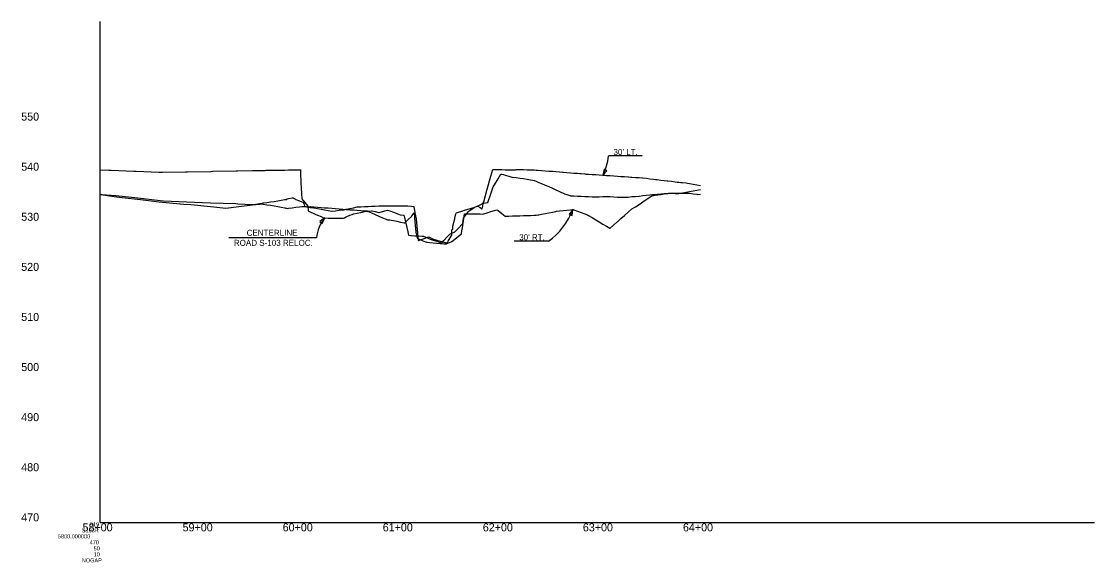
# Model space of a CAD drawing. Extents: x 1961504 to 1964196, y 1107046 to 1115093.
# Drawn here: x 1961505 to 1962577, y 1114552 to 1115093 of the extents above; entities that cross this region are included whole.
import ezdxf

# ---------------------------------------------------------------- set-up
doc = ezdxf.new("R2010")
doc.units = 0
for name, color, linetype in [('Level 40', 7, 'Continuous'), ('Level 41', 7, 'Continuous'), ('Level 42', 7, 'Continuous'), ('Level 63', 7, 'Continuous')]:
    doc.layers.add(name, color=color, linetype=linetype)

msp = doc.modelspace()

# ---------------------------------------------------------------- linework, layer by layer
at = {"layer": 'Level 40'}
for points in [[(1961583.7, 1114944.4), (1961592.3, 1114944), (1961594.7, 1114944), (1961617.3, 1114943.1), (1961619.7, 1114943), (1961642.3, 1114942.2), (1961642.8, 1114942.1), (1961645.9, 1114942), (1961668.8, 1114942.4), (1961670.9, 1114942.5), (1961694.1, 1114942.9), (1961695.9, 1114943), (1961719.5, 1114943.4), (1961720.9, 1114943.4), (1961735.7, 1114943.7), (1961739.3, 1114943.8), (1961742.9, 1114943.8), (1961744.8, 1114943.9), (1961745.9, 1114943.9), (1961745.9, 1114943.9), (1961746.5, 1114943.9), (1961748.4, 1114943.9), (1961749.5, 1114944), (1961750.2, 1114944), (1961753.8, 1114944), (1961757.4, 1114944.1), (1961761, 1114944.2), (1961764.6, 1114944.3), (1961768.2, 1114944.3), (1961771.8, 1114944.4), (1961773.4, 1114944.4), (1961774.2, 1114944.5), (1961775.4, 1114944.5), (1961779.1, 1114944.6), (1961782.7, 1114944.6), (1961783.7, 1114944.6), (1961783.8, 1114944.7), (1961783.9, 1114941.5), (1961784.2, 1114931.5), (1961785.3, 1114915.4), (1961786.3, 1114914.3), (1961789.9, 1114909.8), (1961791.2, 1114908.1), (1961791.5, 1114903.4), (1961793.5, 1114902.4), (1961797.1, 1114900.8), (1961798.5, 1114900.1), (1961800.7, 1114899.2), (1961804.3, 1114897.8), (1961806.9, 1114896.7), (1961807.9, 1114896.4), (1961808, 1114896.4), (1961811.6, 1114896.3), (1961815.2, 1114896.3), (1961818.8, 1114896.3), (1961822.4, 1114896.3), (1961826, 1114896.2), (1961826.8, 1114896.2), (1961827.9, 1114896.6), (1961829.6, 1114897.4), (1961833.2, 1114899.1), (1961835.4, 1114900), (1961836.8, 1114900.4), (1961840.4, 1114901.2), (1961844.1, 1114902), (1961847.7, 1114902.9), (1961848.7, 1114903.1), (1961851.3, 1114903.3), (1961854.9, 1114903.6), (1961855.4, 1114903.6), (1961858.5, 1114902.8), (1961862.1, 1114901.9), (1961862.3, 1114901.9), (1961865.7, 1114902.8), (1961869.3, 1114903.9), (1961870.6, 1114904.2), (1961873, 1114903.4), (1961876.6, 1114902.1), (1961880.2, 1114900.9), (1961883.4, 1114899.7), (1961883.8, 1114899.7), (1961886.7, 1114899.2), (1961887.3, 1114898.5), (1961887.4, 1114898.3), (1961887.8, 1114896.9), (1961891, 1114882.7), (1961891.8, 1114879.2), (1961893.7, 1114878.9), (1961894.6, 1114878.9), (1961898.2, 1114878.7), (1961901.8, 1114878.6), (1961905.5, 1114878.4), (1961906.8, 1114878.3), (1961909.1, 1114877.2), (1961912.7, 1114875.5), (1961913.4, 1114875.1), (1961916.3, 1114874.2), (1961919.9, 1114873.2), (1961923.5, 1114872.1), (1961925.1, 1114871.6), (1961927.1, 1114873.8)], [(1961939.6, 1114901.5), (1961941.6, 1114902.1), (1961945.2, 1114903.2), (1961948.8, 1114904.4), (1961952.4, 1114905.5), (1961956, 1114906.7), (1961958, 1114907.3), (1961959.6, 1114907.8), (1961960.9, 1114908.2), (1961963.2, 1114906.8), (1961965.1, 1114905.7), (1961965.2, 1114905.7), (1961965.7, 1114907), (1961966.8, 1114912.4), (1961966.9, 1114912.5), (1961970.5, 1114925.3), (1961974.1, 1114938.1), (1961976, 1114944.8), (1961977.7, 1114944.8), (1961977.9, 1114944.8), (1961981.3, 1114944.8), (1961984.9, 1114944.7), (1961988.5, 1114944.6), (1961992.1, 1114944.6), (1961995.7, 1114944.5), (1961997.1, 1114944.5), (1961998.7, 1114944.6), (1961999.4, 1114944.7), (1961999.4, 1114944.7), (1962001.5, 1114944.8), (1962003, 1114944.8), (1962006.6, 1114944.7), (1962010.2, 1114944.6), (1962013.8, 1114944.5), (1962017.4, 1114944.4), (1962019.2, 1114944.3), (1962020.5, 1114944.2), (1962020.8, 1114944.2), (1962021, 1114944.2), (1962024.6, 1114943.9), (1962028.2, 1114943.6), (1962031.9, 1114943.3), (1962035.5, 1114943.1), (1962039.1, 1114942.8), (1962042.6, 1114942.5), (1962042.7, 1114942.5), (1962045.5, 1114942.2), (1962046.3, 1114942.2), (1962049.9, 1114941.9), (1962053.5, 1114941.6), (1962057.1, 1114941.3), (1962060.7, 1114941), (1962062.8, 1114940.8), (1962064.4, 1114940.7), (1962068, 1114940.4), (1962068.5, 1114940.3), (1962071.6, 1114940.1), (1962075.2, 1114939.9), (1962078.8, 1114939.7), (1962082.4, 1114939.4), (1962086, 1114939.2), (1962087.9, 1114939), (1962089.6, 1114938.9), (1962092.9, 1114938.7), (1962093.3, 1114938.7), (1962096.9, 1114938.4), (1962100.5, 1114938.2), (1962104.1, 1114937.9), (1962107.7, 1114937.7), (1962111.3, 1114937.4), (1962111.5, 1114937.4), (1962113.9, 1114937.3), (1962114.9, 1114937.2), (1962118.5, 1114936.9), (1962122.1, 1114936.7), (1962125.6, 1114936.4), (1962125.8, 1114936.4), (1962129.4, 1114936), (1962133, 1114935.5), (1962136.6, 1114935.1), (1962138.5, 1114934.9), (1962140.2, 1114934.7), (1962143.8, 1114934.3), (1962147.4, 1114933.9), (1962150.4, 1114933.6), (1962151, 1114933.5), (1962154.6, 1114933), (1962158.3, 1114932.5), (1962160.1, 1114932.3), (1962161.9, 1114932.1), (1962164, 1114931.8), (1962165.5, 1114931.7), (1962169.1, 1114931.4), (1962170.4, 1114931.2), (1962172.7, 1114930.8), (1962176.3, 1114930.1), (1962179.9, 1114929.4), (1962183.5, 1114928.7), (1962183.7, 1114928.7)], [(1961927.1, 1114873.8), (1961930.7, 1114877.9), (1961932.9, 1114880.3), (1961934.3, 1114880.9), (1961937.5, 1114882.3), (1961938, 1114882.7), (1961941.6, 1114886.3), (1961945.2, 1114889.9), (1961946.1, 1114890.8), (1961946.8, 1114896.1), (1961948.8, 1114898.9), (1961951.3, 1114902.6), (1961952.4, 1114903.4), (1961956, 1114905.9), (1961957.8, 1114907.2), (1961959.6, 1114908), (1961963.2, 1114909.7), (1961966.4, 1114911.2), (1961966.9, 1114911.2), (1961967, 1114911.2), (1961970.5, 1114911.7), (1961971.1, 1114911.8), (1961974.1, 1114920.5), (1961976.5, 1114927.5), (1961977.7, 1114929.5), (1961981.3, 1114935.6), (1961984, 1114940.1), (1961984.3, 1114940.1), (1961984.9, 1114940), (1961986.7, 1114939.8), (1961988.5, 1114939.3), (1961992.1, 1114938.2), (1961995.1, 1114937.3), (1961995.7, 1114937.2), (1961999.4, 1114936.7), (1962003, 1114936.2), (1962006.6, 1114935.7), (1962010.2, 1114935.2), (1962013.8, 1114934.6), (1962016.1, 1114934.3), (1962017.4, 1114933.8), (1962017.4, 1114933.7), (1962017.5, 1114933.7), (1962019.3, 1114933), (1962020.7, 1114932.5), (1962021, 1114932.3), (1962024.6, 1114930.8), (1962028.2, 1114929.3), (1962031.9, 1114927.7), (1962035.5, 1114926.1), (1962039.1, 1114924.5), (1962042.7, 1114922.8), (1962044, 1114922.2), (1962046.3, 1114921.2), (1962047.8, 1114920.5), (1962049.9, 1114919.7), (1962053, 1114918.7), (1962053.5, 1114918.6), (1962057.1, 1114918.4), (1962060.7, 1114918.2), (1962060.7, 1114918.2), (1962064.4, 1114918.1), (1962068, 1114918), (1962068, 1114918), (1962071.6, 1114917.8), (1962075.2, 1114917.6), (1962078.8, 1114917.4), (1962078.9, 1114917.4), (1962082.4, 1114917.5), (1962086, 1114917.7), (1962089.6, 1114917.8), (1962093, 1114917.9), (1962093.3, 1114917.8), (1962096.9, 1114917.5), (1962100.5, 1114917.2), (1962100.6, 1114917.2), (1962104.1, 1114917.2), (1962107.7, 1114917.2), (1962110.5, 1114917.2), (1962111.3, 1114917.3), (1962114.9, 1114917.7), (1962118.5, 1114918), (1962122.1, 1114918.3), (1962122.3, 1114918.3), (1962125.8, 1114918.7), (1962129.4, 1114919.2), (1962133, 1114919.5), (1962135.5, 1114919.8), (1962136.6, 1114919.9), (1962140.2, 1114920.3), (1962143.8, 1114920.6), (1962143.8, 1114920.6), (1962147.4, 1114920.8), (1962151, 1114921), (1962154.6, 1114921.1), (1962156.2, 1114921.1), (1962158.3, 1114921), (1962161.6, 1114920.7), (1962161.9, 1114920.8), (1962165.5, 1114921.5), (1962169.1, 1114922.2)], [(1961963.2, 1114900.4), (1961965.9, 1114900.3), (1961966.9, 1114900.6), (1961970.5, 1114901.7), (1961974.1, 1114902.8), (1961977.7, 1114904), (1961980.1, 1114904.7), (1961981.3, 1114903.8), (1961984.9, 1114900.9), (1961988.3, 1114898.2), (1961988.5, 1114898.2), (1961992.1, 1114898.3), (1961995.7, 1114898.4), (1961999.4, 1114898.6), (1962003, 1114898.7), (1962006.6, 1114898.8), (1962010.2, 1114898.9), (1962013.8, 1114899), (1962017.4, 1114899.1), (1962019.4, 1114899.1), (1962021, 1114899.4), (1962022.1, 1114899.5), (1962024.6, 1114900.1), (1962028.2, 1114900.8), (1962031.9, 1114901.5), (1962035.5, 1114902.2), (1962039.1, 1114903), (1962039.6, 1114903.1), (1962042.7, 1114903.4), (1962046.3, 1114903.8), (1962049.9, 1114904.2), (1962053.5, 1114904.6), (1962056.1, 1114904.8), (1962056.4, 1114904.8), (1962057.1, 1114904.6), (1962060.7, 1114903.2), (1962064.4, 1114901.9), (1962068, 1114900.6), (1962070.7, 1114899.5), (1962071.6, 1114899), (1962075.2, 1114896.8), (1962078.8, 1114894.7), (1962082.4, 1114892.5), (1962086, 1114890.3), (1962089.6, 1114888.1), (1962092.9, 1114886.1), (1962093.3, 1114886.4), (1962096.5, 1114889.2), (1962096.9, 1114889.5), (1962100, 1114892.2), (1962100.5, 1114892.7), (1962104.1, 1114895.8), (1962107.7, 1114899), (1962111.3, 1114902.2), (1962114.8, 1114905.4), (1962114.9, 1114905.4), (1962118.5, 1114907.7), (1962122.1, 1114910), (1962125.8, 1114912.4), (1962129.4, 1114914.7), (1962133, 1114917.1), (1962135.4, 1114918.7), (1962136.6, 1114918.9), (1962138.4, 1114919.3), (1962140.2, 1114919.4), (1962140.8, 1114919.5), (1962143.8, 1114919.9), (1962147.4, 1114920.4), (1962151, 1114920.9), (1962152, 1114921.1), (1962154.6, 1114921.1), (1962158.3, 1114921.1), (1962161.9, 1114921.1), (1962165.5, 1114921.1), (1962169.1, 1114921.1), (1962172.2, 1114921.1), (1962172.7, 1114921.1), (1962176.3, 1114920.6), (1962179.9, 1114920.1), (1962180.5, 1114920), (1962183.5, 1114920.1), (1962183.7, 1114920.1)], [(1962169.1, 1114922.2), (1962172.7, 1114922.9), (1962176.3, 1114923.5), (1962179.9, 1114924.2), (1962181.5, 1114924.4), (1962183.5, 1114924.9), (1962183.7, 1114924.9)], [(1961583.7, 1114920.1), (1961585.1, 1114919.9), (1961599.1, 1114919), (1961621.3, 1114916.4), (1961643.6, 1114913.8), (1961647, 1114913.4), (1961669.8, 1114912.6), (1961693.8, 1114911.6), (1961719.3, 1114910.7), (1961721.1, 1114910.6), (1961735.7, 1114910), (1961736.4, 1114910), (1961739.3, 1114910.3), (1961742.9, 1114910.8), (1961744.8, 1114911), (1961746.5, 1114911.5), (1961746.9, 1114911.6), (1961750.2, 1114912), (1961753.8, 1114912.5), (1961757.4, 1114913), (1961761, 1114913.6), (1961764.6, 1114914.2), (1961768.2, 1114914.8), (1961769.5, 1114915), (1961770.6, 1114915.5), (1961771.8, 1114915.7), (1961775.4, 1114916.4), (1961776.2, 1114916.5), (1961778.8, 1114915.1), (1961779.1, 1114915), (1961782.7, 1114913.5), (1961786.3, 1114912.1), (1961786.5, 1114912), (1961787, 1114910.8), (1961787.7, 1114908.2), (1961789.8, 1114907.7), (1961789.9, 1114907.7), (1961793.5, 1114907.8), (1961793.9, 1114907.8), (1961797.1, 1114907.6), (1961800.7, 1114907.3), (1961804.3, 1114907), (1961807.9, 1114906.7), (1961811.6, 1114906.5), (1961815.2, 1114906.2), (1961818.8, 1114905.9), (1961822.4, 1114905.6), (1961826, 1114905.3), (1961829.6, 1114905), (1961833.2, 1114904.7), (1961836.8, 1114904.5), (1961840.4, 1114904.2), (1961844.1, 1114903.9), (1961847.7, 1114903.6), (1961850.5, 1114903.4), (1961851.3, 1114903), (1961854.9, 1114901.4), (1961858.5, 1114899.8), (1961862.1, 1114898.3), (1961865.7, 1114896.7), (1961869.3, 1114895.1), (1961870.7, 1114894.5), (1961873, 1114894.4), (1961874.3, 1114894.3), (1961876.6, 1114893.8), (1961880.2, 1114893.1), (1961883.8, 1114892.3), (1961887.4, 1114891.6), (1961888, 1114891.5), (1961891, 1114894.5), (1961894.6, 1114898), (1961895, 1114898.4), (1961897.5, 1114901.4), (1961898.2, 1114892.7), (1961899.1, 1114882.1), (1961900.4, 1114876.4), (1961901.8, 1114875.7), (1961905.5, 1114873.9), (1961906.9, 1114873.2), (1961908.6, 1114872.7), (1961909.1, 1114872.6), (1961910.1, 1114872.3), (1961912.7, 1114872), (1961916.3, 1114871.7), (1961919.9, 1114871.4), (1961923.5, 1114871.1), (1961927.1, 1114870.7), (1961929.7, 1114870.5), (1961930.7, 1114872.1), (1961931.4, 1114873.2), (1961934.3, 1114878.1), (1961935, 1114879.2), (1961935.2, 1114884), (1961935.3, 1114885.1), (1961936, 1114884.9), (1961936.1, 1114888.1), (1961938, 1114895.4), (1961938.2, 1114896.2), (1961939.1, 1114900.6), (1961939.4, 1114901.1), (1961939.6, 1114901.5)], [(1961583.7, 1114919.8), (1961586.3, 1114919.5), (1961597.5, 1114918), (1961605.7, 1114916.7), (1961624, 1114914.7), (1961642.7, 1114912.6), (1961645.8, 1114912.2), (1961667.3, 1114910.2), (1961674.1, 1114910), (1961697.3, 1114907.5), (1961709.2, 1114906.3), (1961722.1, 1114907.8), (1961735.7, 1114909.5), (1961739.3, 1114909.9), (1961739.5, 1114909.9), (1961742.9, 1114910.3), (1961744.8, 1114910.5), (1961746.5, 1114910.3), (1961750.2, 1114909.7), (1961753.8, 1114909.1), (1961757.4, 1114908.4), (1961761, 1114907.8), (1961764.6, 1114907.1), (1961768.2, 1114906.4), (1961769.1, 1114906.2), (1961769.4, 1114906.2), (1961769.5, 1114906.3), (1961770.5, 1114905.9), (1961771.8, 1114906.1), (1961775.4, 1114906.6), (1961779.1, 1114907.1), (1961782.7, 1114907.6), (1961785.2, 1114907.9), (1961786.3, 1114907.9), (1961789.2, 1114907.8), (1961789.9, 1114907.7), (1961793.5, 1114907), (1961797.1, 1114906.4), (1961800.7, 1114905.8), (1961804.3, 1114905.1), (1961807.9, 1114904.5), (1961811.6, 1114903.9), (1961815.2, 1114903.3), (1961815.3, 1114903.2), (1961818.8, 1114903.7), (1961822.4, 1114904.1), (1961826, 1114904.5), (1961827.6, 1114904.7), (1961829.6, 1114905.2), (1961833.2, 1114905.9), (1961836.8, 1114906.6), (1961840.4, 1114907.4), (1961840.9, 1114907.5), (1961844.1, 1114907.6), (1961847.7, 1114907.8), (1961851.3, 1114908), (1961854.9, 1114908.2), (1961856, 1114908.2), (1961858.5, 1114908.3), (1961862.1, 1114908.4), (1961865.7, 1114908.4), (1961869.3, 1114908.5), (1961873, 1114908.6), (1961874.5, 1114908.6), (1961876.6, 1114908.6), (1961880.2, 1114908.5), (1961883.8, 1114908.5), (1961887.4, 1114908.5), (1961891, 1114908.4), (1961891.2, 1114908.4), (1961894.6, 1114908.1), (1961897.1, 1114907.9), (1961898.2, 1114901.5), (1961899.3, 1114895.5), (1961901.5, 1114873.9), (1961901.8, 1114874), (1961905.5, 1114875.1), (1961906.7, 1114875.5), (1961909.1, 1114876.5), (1961911.7, 1114877.7), (1961912.7, 1114877.2), (1961916.3, 1114875.4), (1961916.7, 1114875.2), (1961919.9, 1114874.3), (1961923.5, 1114873.4), (1961927.1, 1114872.4), (1961930.7, 1114871.4), (1961931, 1114871.4), (1961934.3, 1114872.7), (1961934.9, 1114872.9), (1961938, 1114875.3), (1961941.6, 1114878.2), (1961944.8, 1114880.7), (1961945.2, 1114883.5), (1961945.6, 1114886.6), (1961947.7, 1114900.7), (1961948.8, 1114900.7), (1961952.4, 1114900.6), (1961956, 1114900.5), (1961959.6, 1114900.5), (1961963.2, 1114900.4)]]:
    msp.add_lwpolyline(points, dxfattribs=at)
at = {"layer": 'Level 41'}
for p, q in [((1962125.4, 1114958.3), (1962091.6, 1114958.3)), ((1961799.7, 1114876.6), (1961712.2, 1114876.6)), ((1962031.7, 1114873.2), (1961997.4, 1114873.2))]:
    msp.add_line(p, q, dxfattribs=at)
for points in [[(1962087.3, 1114945), (1962086, 1114939.2), (1962090.1, 1114943.6)], [(1962055.2, 1114898.8), (1962055.8, 1114904.8), (1962052.3, 1114899.9)], [(1961805.5, 1114890.9), (1961808, 1114896.4), (1961803.1, 1114892.9)]]:
    msp.add_lwpolyline(points, close=True, dxfattribs=at)
for centre, radius, start, end in [((1962040, 1114962.9), 51.8, 332.6976, 354.8337), ((1961990.3, 1114929.7), 70.1, 306.2312, 339.1826), ((1961836.6, 1114872.8), 37.1, 140.5163, 174.0816)]:
    msp.add_arc(centre, radius, start, end, dxfattribs=at)
at = {"layer": 'Level 63'}
for q in [(1961583.7, 1115092.6), (1962577.3, 1114592.6), (1961583.7, 1114592.6)]:
    msp.add_line((1961583.7, 1114592.6), q, dxfattribs=at)

# ---------------------------------------------------------------- texts
at = {"layer": 'Level 41'}
for s, p in [("30' LT.", (1962096.6, 1114959.3)), ('CENTERLINE', (1961730, 1114878.6)), ("30' RT.", (1962002.4, 1114874.2)), ('ROAD S-103 RELOC.', (1961717.2, 1114868.6))]:
    msp.add_text(s, height=6, dxfattribs=at).set_placement(p)
at = {"layer": 'Level 42'}
for s, p in [('550', (1961504.7, 1114993.6)), ('540', (1961504.7, 1114943.6)), ('530', (1961504.7, 1114893.6)), ('520', (1961504.7, 1114843.6)), ('510', (1961504.7, 1114793.6)), ('500', (1961504.7, 1114743.6)), ('490', (1961504.7, 1114693.6)), ('480', (1961504.7, 1114643.6)), ('470', (1961504.7, 1114593.6)), ('58+00', (1961566, 1114583.6)), ('59+00', (1961666, 1114583.6)), ('60+00', (1961766, 1114583.6)), ('61+00', (1961866, 1114583.6)), ('62+00', (1961966, 1114583.6)), ('63+00', (1962066, 1114583.6)), ('64+00', (1962166, 1114583.6))]:
    msp.add_text(s, height=8, dxfattribs=at).set_placement(p)
at = {"layer": 'Level 63'}
for s, p in [('919', (1961573.4, 1114588.6)), ('5800.000000', (1961541.3, 1114576.6)), ('S103R', (1961565.3, 1114582.6)), ('470', (1961573.1, 1114570.6)), ('50', (1961577.1, 1114564.6)), ('NOGAP', (1961565.3, 1114552.6)), ('10', (1961577.1, 1114558.6))]:
    msp.add_text(s, height=4, dxfattribs=at).set_placement(p)

doc.saveas('drawing.dxf')
